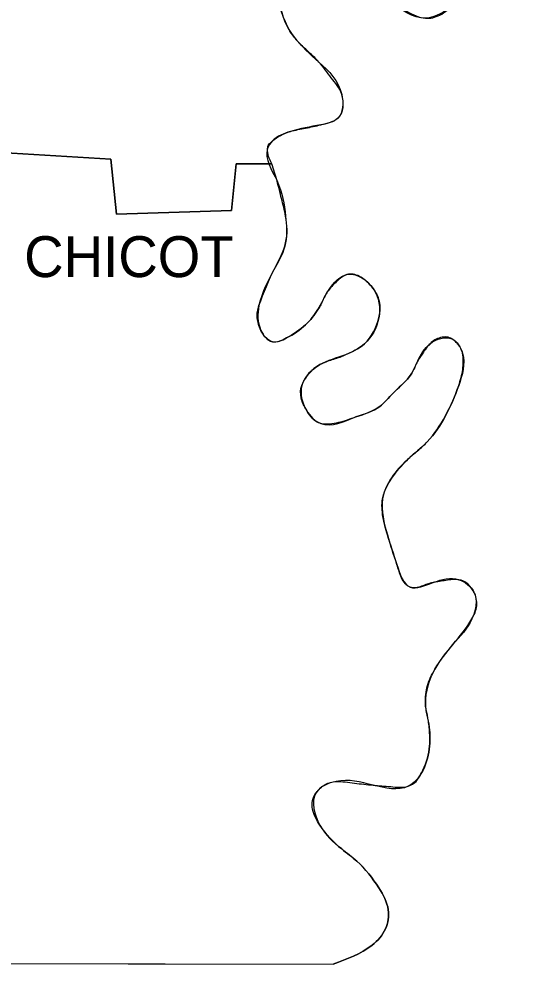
# Model space of a CAD drawing. Extents: x 1368042 to 1371376, y 380392 to 382637.
# Drawn here: x 1369949.8 to 1370061.6, y 380633.7 to 380841.2 of the extents above; entities that cross this region are included whole.
import ezdxf

# ---------------------------------------------------------------- set-up
doc = ezdxf.new("R2010")
doc.units = 0
doc.layers.add('Default', color=7, linetype='Continuous')
doc.layers.add('R_No Plot', color=7, linetype='Continuous')

msp = doc.modelspace()

# ---------------------------------------------------------------- linework, layer by layer
at = {"layer": 'Default'}
for points in [[(1369940.93, 380812.13), (1369969.96, 380810.4), (1369971.21, 380798.29), (1369996.48, 380799.12), (1369997.52, 380809.35), (1370005.33, 380809.35)], [(1369253.07, 380803.93), (1369253.48, 380634.99), (1370018.82, 380633.74)]]:
    msp.add_lwpolyline(points, dxfattribs=at)
msp.add_spline([(1370050.77, 380921.49), (1370048.68, 380916.69), (1370046.39, 380908.33), (1370047.01, 380901.23), (1370050.15, 380895.18), (1370055.16, 380891.84), (1370060.59, 380887.03), (1370060.17, 380879.73), (1370057.04, 380877.01), (1370049.73, 380878.89), (1370044.09, 380881.4), (1370039.29, 380879.94), (1370032.81, 380876.8), (1370028.01, 380876.18), (1370028.22, 380866.15), (1370034.69, 380859.05), (1370040.33, 380859.05), (1370046.8, 380858.22), (1370049.1, 380850.7), (1370045.34, 380844.44), (1370039.08, 380841.3), (1370031.14, 380845.06), (1370025.5, 380849.03), (1370019.87, 380852.79), (1370012.77, 380854.67), (1370008.8, 380853.83), (1370006.92, 380845.06), (1370010.26, 380837.13), (1370015.69, 380831.7), (1370020.7, 380824.6), (1370019.87, 380819.38), (1370016.11, 380817.92), (1370009.43, 380816.45), (1370005.46, 380814.37), (1370004.41, 380812.7), (1370006.5, 380805.6), (1370008.38, 380797.87), (1370008.38, 380792.02), (1370006.08, 380786.59), (1370002.53, 380778.24), (1370002.95, 380772.81), (1370005.46, 380770.31), (1370008.59, 380771.14), (1370012.77, 380774.06), (1370015.48, 380777.41), (1370017.78, 380781.58), (1370022.16, 380785.13), (1370027.59, 380782), (1370028.85, 380775.53), (1370025.71, 380769.89), (1370021.33, 380767.38), (1370015.9, 380765.29), (1370011.93, 380760.7), (1370012.98, 380755.27), (1370016.11, 380752.35), (1370023.83, 380753.81), (1370029.05, 380756.11), (1370031.98, 380759.03), (1370035.53, 380762.58), (1370037.41, 380766.13), (1370040.12, 380769.89), (1370044.93, 380770.93), (1370047.22, 380767.8), (1370046.39, 380760.7), (1370043.46, 380754.02), (1370039.5, 380748.38), (1370035.11, 380744.41), (1370029.68, 380735.85), (1370030.73, 380727.92), (1370032.81, 380721.44), (1370035.74, 380716.43), (1370040.75, 380717.47), (1370046.39, 380718.1), (1370049.73, 380715.39), (1370049.31, 380709.54), (1370045.13, 380703.9), (1370041.17, 380698.47), (1370039.08, 380690.95), (1370039.91, 380685.73), (1370039.91, 380680.93), (1370038.24, 380675.71), (1370035.32, 380672.79), (1370027.59, 380673), (1370019.45, 380673.83), (1370015.06, 380671.33), (1370015.9, 380664.23), (1370020.7, 380659), (1370024.04, 380656.29), (1370028.85, 380650.44), (1370030.93, 380645.64), (1370030.31, 380641.46), (1370027.38, 380637.91), (1370018.82, 380633.74)], degree=3, dxfattribs=at)
at = {"layer": 'R_No Plot'}
for p, q in [((1369940.93, 380812.13), (1369969.96, 380810.4)), ((1369969.96, 380810.4), (1369971.21, 380798.29)), ((1369996.48, 380799.12), (1369997.52, 380809.35)), ((1369997.52, 380809.35), (1370005.34, 380809.36)), ((1369971.21, 380798.29), (1369996.48, 380799.12)), ((1369942.6, 380633.86), (1370018.82, 380633.74))]:
    msp.add_line(p, q, dxfattribs=at)
for points in [[(1370005.33, 380809.35), (1369997.52, 380809.35), (1369996.48, 380799.12), (1369971.21, 380798.29), (1369969.96, 380810.4), (1369940.93, 380812.13)], [(1370005.34, 380809.36), (1370005.33, 380809.35)]]:
    msp.add_lwpolyline(points, dxfattribs=at)
for points in [[(1370011.82, 380835.39), (1370010.26, 380837.13), (1370008.12, 380841), (1370006.92, 380845.06), (1370006.54, 380847.23), (1370006.54, 380849.49), (1370007.2, 380851.73), (1370008.8, 380853.83), (1370009.29, 380854.22), (1370009.78, 380854.5), (1370010.78, 380854.77), (1370012.77, 380854.67), (1370014.56, 380854.43), (1370016.37, 380854.11), (1370019.87, 380852.79), (1370025.5, 380849.03), (1370031.14, 380845.06), (1370035.08, 380842.77), (1370039.08, 380841.3), (1370042.22, 380841.98), (1370045.34, 380844.44), (1370046.77, 380845.95), (1370047.82, 380847.5), (1370049.1, 380850.7), (1370049.36, 380852.64), (1370049.15, 380854.75), (1370048.34, 380856.71), (1370046.8, 380858.22), (1370046, 380858.62), (1370045.19, 380858.88), (1370043.58, 380859.07), (1370040.33, 380859.05), (1370038.92, 380859.04), (1370037.51, 380858.92), (1370036.1, 380858.88), (1370034.69, 380859.05), (1370033.57, 380859.47), (1370032.57, 380860.1), (1370030.88, 380861.86), (1370028.22, 380866.15), (1370027.6, 380867.33), (1370026.38, 380871.49), (1370026.58, 380874.17), (1370027.12, 380875.29), (1370028.01, 380876.18), (1370028.56, 380876.46), (1370029.15, 380876.59), (1370030.39, 380876.62), (1370031.64, 380876.57), (1370032.81, 380876.8), (1370034.42, 380877.56), (1370036.02, 380878.37), (1370037.63, 380879.18), (1370039.29, 380879.94), (1370041.69, 380880.94), (1370044.09, 380881.4), (1370044.81, 380881.29), (1370045.52, 380881.07), (1370046.92, 380880.37), (1370048.32, 380879.56), (1370049.73, 380878.89), (1370053.35, 380877.6), (1370057.04, 380877.01), (1370058.78, 380877.92), (1370059.51, 380878.78), (1370060.17, 380879.73), (1370061.09, 380881.55), (1370061.54, 380883.53), (1370061.41, 380885.44), (1370060.59, 380887.03), (1370058, 380889.56), (1370055.16, 380891.84), (1370053.91, 380892.67), (1370052.62, 380893.42), (1370051.35, 380894.22), (1370050.15, 380895.18), (1370047.01, 380901.23), (1370046.39, 380908.33), (1370047.39, 380912.55), (1370048.68, 380916.69), (1370049.19, 380917.9), (1370049.8, 380919.1), (1370050.38, 380920.29), (1370050.77, 380921.49)], [(1370005.34, 380809.36), (1370004.41, 380812.7), (1370004.68, 380813.59), (1370005.04, 380813.99), (1370005.46, 380814.37), (1370009.43, 380816.45), (1370011.09, 380816.87), (1370012.76, 380817.21), (1370014.44, 380817.53), (1370016.11, 380817.92), (1370018.03, 380818.45), (1370018.96, 380818.83), (1370019.87, 380819.38), (1370020.7, 380824.6), (1370018.41, 380828.23), (1370015.69, 380831.7), (1370013.79, 380833.59), (1370011.82, 380835.39)], [(1370047.19, 380767.95), (1370046.35, 380769.63), (1370045.68, 380770.34), (1370044.93, 380770.93), (1370043.75, 380771.34), (1370042.42, 380771.23), (1370041.15, 380770.71), (1370040.12, 380769.89), (1370038.67, 380768.06), (1370037.41, 380766.13), (1370036.96, 380765.22), (1370036.57, 380764.27), (1370035.53, 380762.58), (1370031.98, 380759.03), (1370029.05, 380756.11), (1370023.83, 380753.81), (1370019.98, 380752.56), (1370018.02, 380752.25), (1370016.11, 380752.35), (1370014.36, 380753.41), (1370012.98, 380755.27), (1370011.78, 380758.01), (1370011.93, 380760.7), (1370012.6, 380762.03), (1370013.5, 380763.28), (1370015.9, 380765.29), (1370017.25, 380765.92), (1370018.62, 380766.4), (1370019.99, 380766.84), (1370021.33, 380767.38), (1370025.71, 380769.89), (1370028.85, 380775.53), (1370029.12, 380777.1), (1370029.07, 380778.75), (1370028.59, 380780.4), (1370027.59, 380782), (1370026.29, 380783.39), (1370024.89, 380784.49), (1370022.16, 380785.13), (1370019.87, 380783.79), (1370017.78, 380781.58), (1370017.1, 380780.54), (1370016.57, 380779.47), (1370016.08, 380778.42), (1370015.48, 380777.41), (1370012.77, 380774.06), (1370008.59, 380771.14), (1370007.04, 380770.41), (1370005.46, 380770.31), (1370004.01, 380771.23), (1370002.95, 380772.81), (1370002.42, 380774.17), (1370002.15, 380775.56), (1370002.18, 380776.94), (1370002.53, 380778.24), (1370006.08, 380786.59), (1370008.38, 380792.02), (1370008.38, 380797.87), (1370007.48, 380801.74), (1370006.5, 380805.6), (1370005.34, 380809.36)], [(1370018.82, 380633.74), (1370027.38, 380637.91), (1370030.31, 380641.46), (1370030.93, 380645.64), (1370028.85, 380650.44), (1370024.04, 380656.29), (1370020.7, 380659), (1370015.9, 380664.23), (1370014.31, 380667.72), (1370014.29, 380669.63), (1370015.06, 380671.33), (1370016, 380672.32), (1370017.06, 380673.13), (1370019.45, 380673.83), (1370021.48, 380673.7), (1370023.52, 380673.46), (1370025.56, 380673.2), (1370027.59, 380673), (1370031.46, 380672.69), (1370035.32, 380672.79), (1370037.03, 380673.84), (1370037.68, 380674.74), (1370038.24, 380675.71), (1370039.91, 380680.93), (1370039.91, 380685.73), (1370039.74, 380687.04), (1370039.46, 380688.35), (1370039.21, 380689.65), (1370039.08, 380690.95), (1370039.17, 380692.91), (1370039.53, 380694.87), (1370041.17, 380698.47), (1370045.13, 380703.9), (1370049.31, 380709.54), (1370050.34, 380712.38), (1370049.73, 380715.39), (1370049.09, 380716.36), (1370048.31, 380717.22), (1370046.39, 380718.1), (1370043.57, 380717.92), (1370040.75, 380717.47), (1370039.48, 380717.12), (1370038.22, 380716.64), (1370036.96, 380716.31), (1370035.74, 380716.43), (1370035.12, 380716.76), (1370034.61, 380717.24), (1370033.85, 380718.5), (1370032.81, 380721.44), (1370030.73, 380727.92), (1370029.76, 380731.89), (1370029.68, 380735.85), (1370029.99, 380737.05), (1370030.45, 380738.2), (1370031.73, 380740.39), (1370035.11, 380744.41), (1370036.2, 380745.45), (1370037.34, 380746.39), (1370038.46, 380747.33), (1370039.5, 380748.38), (1370043.46, 380754.02), (1370046.39, 380760.7), (1370047.28, 380764.22), (1370047.22, 380767.8), (1370047.19, 380767.95)]]:
    msp.add_spline(points, degree=3, dxfattribs=at)

# ---------------------------------------------------------------- texts
at = {"layer": 'Default'}
msp.add_text('CHICOT', height=8.979, dxfattribs=at).set_placement((1369950.95, 380784.5))

doc.saveas('drawing.dxf')
